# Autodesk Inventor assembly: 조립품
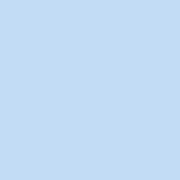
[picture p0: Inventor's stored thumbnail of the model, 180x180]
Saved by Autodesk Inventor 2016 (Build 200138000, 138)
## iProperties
Created: 2018-11
Part Number: 조립품
Material: 일반
Document SubType Name: Assembly
Designer: 공506_41
Author: 공506_41
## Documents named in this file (1)
- C:\Users\공506_41\Desktop\새 폴더 (2)\481111V1011\조립품.iam
